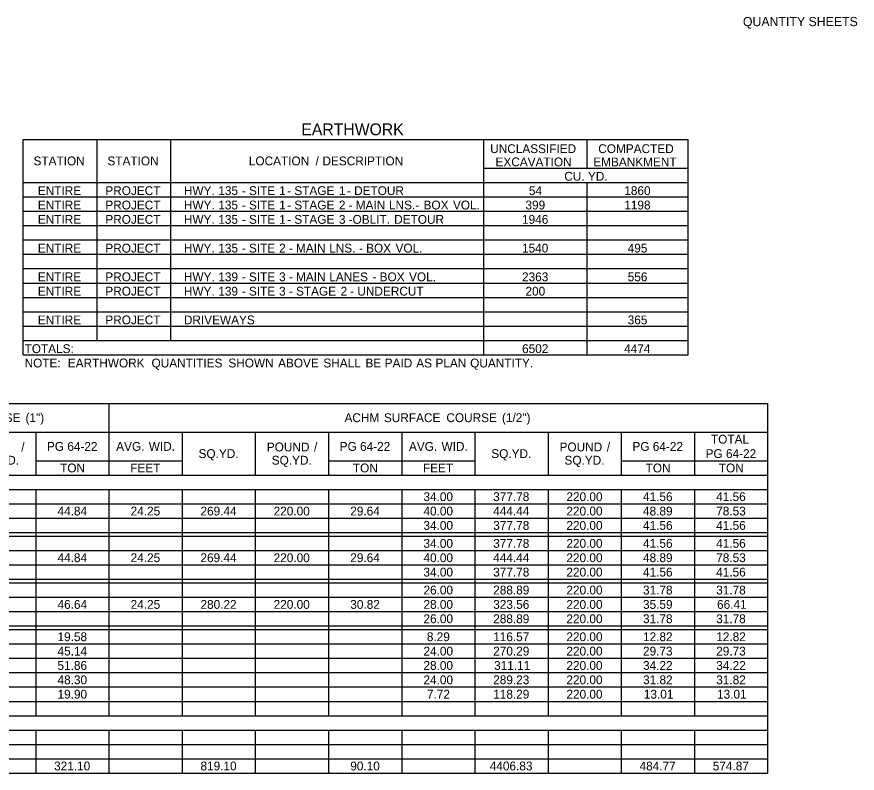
# Model space of a CAD drawing. Extents: x 1955554 to 1962042, y 565952 to 568347.
# Drawn here: x 1959623 to 1960194, y 566455 to 566969 of the extents above; entities that cross this region are included whole.
import ezdxf

# ---------------------------------------------------------------- set-up
doc = ezdxf.new("R2010")
doc.units = 0
doc.layers.add('Default', color=7, linetype='Continuous')
doc.layers.add('STAMP', color=7, linetype='Continuous')

msp = doc.modelspace()

# ---------------------------------------------------------------- linework, layer by layer
at = {"layer": 'Default'}
for p, q in [((1959627.42, 566885.45), (1960079.33, 566885.45)), ((1959627.42, 566739.2), (1959627.42, 566885.45)), ((1959627.42, 566739.2), (1959627.42, 566885.45)), ((1959677.63, 566748.95), (1959677.63, 566885.45)), ((1959727.84, 566748.95), (1959727.84, 566885.45)), ((1959940.39, 566739.2), (1959940.39, 566885.45)), ((1960010.59, 566865.95), (1960010.59, 566885.45)), ((1960079.33, 566739.2), (1960079.33, 566885.45)), ((1960079.33, 566739.2), (1960079.33, 566885.45)), ((1959940.39, 566865.95), (1960079.33, 566865.95)), ((1959627.42, 566856.2), (1960079.33, 566856.2)), ((1959677.63, 566748.95), (1959677.63, 566856.2)), ((1959727.84, 566826.95), (1959727.84, 566856.2)), ((1959940.39, 566826.95), (1959940.39, 566856.2)), ((1960010.59, 566739.2), (1960010.59, 566856.2)), ((1959627.42, 566846.45), (1960079.33, 566846.45)), ((1959627.42, 566836.7), (1960079.33, 566836.7)), ((1959627.42, 566826.95), (1960079.33, 566826.95)), ((1959627.42, 566817.2), (1960079.33, 566817.2)), ((1959727.84, 566748.95), (1959727.84, 566817.2)), ((1959940.39, 566748.95), (1959940.39, 566817.2)), ((1959627.42, 566807.45), (1960079.33, 566807.45)), ((1959627.42, 566797.7), (1960079.33, 566797.7)), ((1959627.42, 566787.95), (1960079.33, 566787.95)), ((1959627.42, 566778.2), (1960079.33, 566778.2)), ((1959627.42, 566768.45), (1960079.33, 566768.45)), ((1959627.42, 566758.7), (1960079.33, 566758.7)), ((1959627.42, 566748.95), (1959677.63, 566748.95)), ((1959627.42, 566748.95), (1960079.33, 566748.95)), ((1959627.42, 566739.2), (1960079.33, 566739.2)), ((1958693.85, 566706.28), (1960133.43, 566706.28)), ((1959685.91, 566686.78), (1959685.91, 566706.28)), ((1959685.91, 566657.53), (1959685.91, 566706.28)), ((1960133.43, 566455.22), (1960133.43, 566706.28)), ((1960133.43, 566455.22), (1960133.43, 566706.28)), ((1959033.15, 566686.78), (1960133.43, 566686.78)), ((1959636.18, 566657.53), (1959636.18, 566686.78)), ((1959735.63, 566686.78), (1959785.36, 566686.78)), ((1959735.63, 566657.53), (1959735.63, 566686.78)), ((1959785.36, 566657.53), (1959785.36, 566686.78)), ((1959835.08, 566657.53), (1959835.08, 566686.78)), ((1959884.81, 566657.53), (1959884.81, 566686.78)), ((1959934.53, 566686.78), (1959984.26, 566686.78)), ((1959934.53, 566657.53), (1959934.53, 566686.78)), ((1959984.26, 566657.53), (1959984.26, 566686.78)), ((1960033.98, 566657.53), (1960033.98, 566686.78)), ((1960083.71, 566657.53), (1960083.71, 566686.78)), ((1959636.18, 566667.28), (1959735.63, 566667.28)), ((1959685.91, 566657.53), (1959685.91, 566667.28)), ((1959735.63, 566657.53), (1959735.63, 566667.28)), ((1959835.08, 566667.28), (1959934.53, 566667.28)), ((1959884.81, 566657.53), (1959884.81, 566667.28)), ((1959934.53, 566657.53), (1959934.53, 566667.28)), ((1960033.98, 566667.28), (1960133.43, 566667.28)), ((1958693.85, 566657.53), (1960133.43, 566657.53)), ((1959536.73, 566657.53), (1959735.63, 566657.53)), ((1959735.63, 566657.53), (1959934.53, 566657.53)), ((1959934.53, 566657.53), (1960133.43, 566657.53)), ((1958693.85, 566647.78), (1960133.43, 566647.78)), ((1959636.18, 566494.22), (1959636.18, 566647.78)), ((1959636.18, 566494.22), (1959636.18, 566647.78)), ((1959685.91, 566494.22), (1959685.91, 566647.78)), ((1959685.91, 566494.22), (1959685.91, 566647.78)), ((1959735.63, 566494.22), (1959735.63, 566647.78)), ((1959735.63, 566494.22), (1959735.63, 566647.78)), ((1959785.36, 566494.22), (1959785.36, 566647.78)), ((1959785.36, 566494.22), (1959785.36, 566647.78)), ((1959835.08, 566494.22), (1959835.08, 566647.78)), ((1959835.08, 566494.22), (1959835.08, 566647.78)), ((1959884.81, 566494.22), (1959884.81, 566647.78)), ((1959884.81, 566494.22), (1959884.81, 566647.78)), ((1959934.53, 566494.22), (1959934.53, 566647.78)), ((1959934.53, 566494.22), (1959934.53, 566647.78)), ((1959984.26, 566494.22), (1959984.26, 566647.78)), ((1959984.26, 566494.22), (1959984.26, 566647.78)), ((1960033.98, 566494.22), (1960033.98, 566647.78)), ((1960033.98, 566494.22), (1960033.98, 566647.78)), ((1960083.71, 566494.22), (1960083.71, 566647.78)), ((1960083.71, 566494.22), (1960083.71, 566647.78)), ((1958693.85, 566638.03), (1960133.43, 566638.03)), ((1958693.85, 566628.28), (1960133.43, 566628.28)), ((1958693.85, 566618.53), (1960133.43, 566618.53)), ((1958693.85, 566616.09), (1960133.43, 566616.09)), ((1958693.85, 566606.34), (1960133.43, 566606.34)), ((1958693.85, 566596.59), (1960133.43, 566596.59)), ((1958693.85, 566586.84), (1960133.43, 566586.84)), ((1958693.85, 566584.4), (1960133.43, 566584.4)), ((1958693.85, 566574.65), (1960133.43, 566574.65)), ((1958693.85, 566564.9), (1960133.43, 566564.9)), ((1958693.85, 566555.15), (1960133.43, 566555.15)), ((1958693.85, 566552.72), (1960133.43, 566552.72)), ((1958693.85, 566542.97), (1960133.43, 566542.97)), ((1958693.85, 566533.22), (1960133.43, 566533.22)), ((1958693.85, 566523.47), (1960133.43, 566523.47)), ((1958693.85, 566513.72), (1960133.43, 566513.72)), ((1958693.85, 566503.97), (1960133.43, 566503.97)), ((1958693.85, 566494.22), (1960133.43, 566494.22)), ((1958693.85, 566494.22), (1960133.43, 566494.22)), ((1958693.85, 566484.47), (1960133.43, 566484.47)), ((1959636.18, 566455.22), (1959636.18, 566484.47)), ((1959636.18, 566455.22), (1959636.18, 566484.47)), ((1959685.91, 566455.22), (1959685.91, 566484.47)), ((1959685.91, 566455.22), (1959685.91, 566484.47)), ((1959735.63, 566455.22), (1959735.63, 566484.47)), ((1959735.63, 566455.22), (1959735.63, 566484.47)), ((1959785.36, 566455.22), (1959785.36, 566484.47)), ((1959785.36, 566455.22), (1959785.36, 566484.47)), ((1959835.08, 566455.22), (1959835.08, 566484.47)), ((1959835.08, 566455.22), (1959835.08, 566484.47)), ((1959884.81, 566455.22), (1959884.81, 566484.47)), ((1959884.81, 566455.22), (1959884.81, 566484.47)), ((1959934.53, 566455.22), (1959934.53, 566484.47)), ((1959934.53, 566455.22), (1959934.53, 566484.47)), ((1959984.26, 566455.22), (1959984.26, 566484.47)), ((1959984.26, 566455.22), (1959984.26, 566484.47)), ((1960033.98, 566455.22), (1960033.98, 566484.47)), ((1960033.98, 566455.22), (1960033.98, 566484.47)), ((1960083.71, 566455.22), (1960083.71, 566484.47)), ((1960083.71, 566455.22), (1960083.71, 566484.47)), ((1958693.85, 566474.72), (1960133.43, 566474.72)), ((1958693.85, 566464.97), (1960133.43, 566464.97)), ((1958693.85, 566455.22), (1960133.43, 566455.22))]:
    msp.add_line(p, q, dxfattribs=at)

# ---------------------------------------------------------------- texts
for s, height, p in [('EARTHWORK', 8, (1959816.43, 566888.28)), ('UNCLASSIFIED', 6, (1959944.72, 566876.15)), ('COMPACTED', 6, (1960018.15, 566876.15)), ('STATION', 6, (1959634.46, 566867.83)), ('STATION', 6, (1959684.67, 566867.83)), ('LOCATION', 6, (1959780.75, 566867.83)), (' /', 6, (1959823.86, 566867.83)), (' DESCRIPTION', 6, (1959828.53, 566867.83)), ('EXCAVATION', 6, (1959948.34, 566867.15)), ('EMBANKMENT', 6, (1960014.77, 566867.15)), ('CU.', 6, (1959995.07, 566857.4)), (' YD.', 6, (1960008.93, 566857.4)), ('ENTIRE', 6, (1959637.37, 566847.65)), ('PROJECT', 6, (1959683.25, 566847.65)), ('HWY.', 6, (1959736.62, 566847.65)), (' 135', 6, (1959757.77, 566847.65)), (' -', 6, (1959773.75, 566847.65)), (' SITE', 6, (1959778.6, 566847.65)), (' 1', 6, (1959799.12, 566847.65)), (' -', 6, (1959804.57, 566847.65)), (' STAGE', 6, (1959809.42, 566847.65)), (' 1', 6, (1959839.72, 566847.65)), (' -', 6, (1959845.17, 566847.65)), (' DETOUR', 6, (1959850.03, 566847.65)), ('54', 6, (1959971.04, 566847.65)), ('1860', 6, (1960035.84, 566847.65)), ('ENTIRE', 6, (1959637.37, 566837.9)), ('PROJECT', 6, (1959683.25, 566837.9)), ('HWY.', 6, (1959736.62, 566837.9)), (' 135', 6, (1959757.77, 566837.9)), (' SITE', 6, (1959778.6, 566837.9)), (' 1', 6, (1959799.12, 566837.9)), (' STAGE', 6, (1959809.42, 566837.9)), (' 2', 6, (1959839.72, 566837.9)), (' MAIN', 6, (1959851.12, 566837.9)), (' LNS.-', 6, (1959873.73, 566837.9)), (' BOX', 6, (1959897.22, 566837.9)), (' VOL.', 6, (1959917.2, 566837.9)), ('399', 6, (1959968.69, 566837.9)), ('1198', 6, (1960035.83, 566837.9)), (' -', 6, (1959773.75, 566837.9)), (' -', 6, (1959804.57, 566837.9)), (' -', 6, (1959846.27, 566837.9)), ('ENTIRE', 6, (1959637.37, 566828.15)), ('PROJECT', 6, (1959683.25, 566828.15)), ('HWY.', 6, (1959736.62, 566828.15)), (' 135', 6, (1959757.77, 566828.15)), (' SITE', 6, (1959778.6, 566828.15)), (' 1', 6, (1959799.12, 566828.15)), (' STAGE', 6, (1959809.42, 566828.15)), (' 3', 6, (1959839.72, 566828.15)), (' -OBLIT.', 6, (1959846.33, 566828.15)), (' DETOUR', 6, (1959877.27, 566828.15)), ('1946', 6, (1959966.36, 566828.15)), (' -', 6, (1959773.75, 566828.15)), (' -', 6, (1959804.57, 566828.15)), ('ENTIRE', 6, (1959637.37, 566808.65)), ('PROJECT', 6, (1959683.25, 566808.65)), ('HWY.', 6, (1959736.62, 566808.65)), (' 135', 6, (1959757.77, 566808.65)), (' SITE', 6, (1959778.6, 566808.65)), (' 2', 6, (1959799.12, 566808.65)), (' MAIN', 6, (1959810.52, 566808.65)), (' LNS.', 6, (1959833.12, 566808.65)), (' BOX', 6, (1959858.21, 566808.65)), (' VOL.', 6, (1959878.19, 566808.65)), ('1540', 6, (1959966.37, 566808.65)), ('495', 6, (1960038.14, 566808.65)), (' -', 6, (1959773.75, 566808.65)), (' -', 6, (1959805.66, 566808.65)), (' -', 6, (1959853.35, 566808.65)), ('ENTIRE', 6, (1959637.37, 566789.15)), ('PROJECT', 6, (1959683.25, 566789.15)), ('HWY.', 6, (1959736.62, 566789.15)), (' 139', 6, (1959757.77, 566789.15)), (' -', 6, (1959773.71, 566789.15)), (' SITE', 6, (1959778.57, 566789.15)), (' 3', 6, (1959799.08, 566789.15)), (' -', 6, (1959805.69, 566789.15)), (' MAIN', 6, (1959810.55, 566789.15)), (' LANES', 6, (1959833.15, 566789.15)), (' -', 6, (1959862.53, 566789.15)), (' BOX', 6, (1959867.39, 566789.15)), (' VOL.', 6, (1959887.37, 566789.15)), ('2363', 6, (1959966.36, 566789.15)), ('556', 6, (1960038.16, 566789.15)), ('ENTIRE', 6, (1959637.37, 566779.4)), ('PROJECT', 6, (1959683.25, 566779.4)), ('HWY.', 6, (1959736.62, 566779.4)), (' 139', 6, (1959757.77, 566779.4)), (' -', 6, (1959773.71, 566779.4)), (' SITE', 6, (1959778.57, 566779.4)), (' 3', 6, (1959799.08, 566779.4)), (' -', 6, (1959805.69, 566779.4)), (' STAGE', 6, (1959810.55, 566779.4)), (' 2', 6, (1959840.85, 566779.4)), (' -', 6, (1959847.39, 566779.4)), (' UNDERCUT', 6, (1959852.25, 566779.4)), ('200', 6, (1959968.7, 566779.4)), ('ENTIRE', 6, (1959637.37, 566759.9)), ('PROJECT', 6, (1959683.25, 566759.9)), ('DRIVEWAYS', 6, (1959736.62, 566759.9)), ('365', 6, (1960038.14, 566759.9)), ('TOTALS:', 6, (1959628.39, 566740.4)), ('6502', 6, (1959966.38, 566740.4)), ('4474', 6, (1960035.74, 566740.4)), ('NOTE:', 6, (1959628.39, 566730.65)), ('  EARTHWORK', 6, (1959653.28, 566730.65)), (' QUANTITIES', 6, (1959712.41, 566730.65)), (' SHOWN', 6, (1959764.61, 566730.65)), (' ABOVE', 6, (1959798.39, 566730.65)), (' SHALL', 6, (1959829.16, 566730.65)), (' BE', 6, (1959857.75, 566730.65)), (' PAID', 6, (1959870.82, 566730.65)), (' AS', 6, (1959892.27, 566730.65)), (' PLAN', 6, (1959905.34, 566730.65)), (' QUANTITY.', 6, (1959928.89, 566730.65)), (' COURSE', 6, (1959589, 566693.53)), (' (1")', 6, (1959626.78, 566693.53)), ('ACHM', 6, (1959845.74, 566693.53)), (' SURFACE', 6, (1959870.29, 566693.53)), (' COURSE', 6, (1959912.73, 566693.53)), (' (1/2")', 6, (1959950.51, 566693.53)), ('TOTAL', 6, (1960094.73, 566678.9)), (' /', 6, (1959623.92, 566673.65)), ('PG', 6, (1959643.57, 566674.03)), (' 64-22', 6, (1959655.18, 566674.03)), ('AVG.', 6, (1959690.62, 566674.03)), (' WID.', 6, (1959710.54, 566674.03)), ('POUND', 6, (1959792.96, 566673.65)), (' /', 6, (1959822.82, 566673.65)), ('PG', 6, (1959842.47, 566674.03)), (' 64-22', 6, (1959854.08, 566674.03)), ('AVG.', 6, (1959889.52, 566674.03)), (' WID.', 6, (1959909.44, 566674.03)), ('POUND', 6, (1959991.86, 566673.65)), (' /', 6, (1960021.72, 566673.65)), ('PG', 6, (1960041.37, 566674.03)), (' 64-22', 6, (1960052.98, 566674.03)), ('SQ.YD.', 6, (1959746.57, 566669.15)), ('SQ.YD.', 6, (1959945.47, 566669.15)), ('PG', 6, (1960091.1, 566669.15)), (' 64-22', 6, (1960102.71, 566669.15)), ('SQ.YD.', 6, (1959597.4, 566664.65)), ('SQ.YD.', 6, (1959796.3, 566664.65)), ('SQ.YD.', 6, (1959995.2, 566664.65)), ('TON', 6, (1959652.53, 566659.4)), ('FEET', 6, (1959700.14, 566659.4)), ('TON', 6, (1959851.43, 566659.4)), ('FEET', 6, (1959899.04, 566659.4)), ('TON', 6, (1960050.33, 566659.4)), ('TON', 6, (1960100.06, 566659.4)), ('34.00', 6, (1959899.39, 566639.9)), ('377.78', 6, (1959946.77, 566639.9)), ('220.00', 6, (1959996.51, 566639.9)), ('41.56', 6, (1960048.55, 566639.9)), ('41.56', 6, (1960098.28, 566639.9)), ('44.84', 6, (1959650.76, 566630.15)), ('24.25', 6, (1959700.45, 566630.15)), ('269.44', 6, (1959747.88, 566630.15)), ('220.00', 6, (1959797.61, 566630.15)), ('29.64', 6, (1959849.66, 566630.15)), ('40.00', 6, (1959899.39, 566630.15)), ('444.44', 6, (1959946.78, 566630.15)), ('220.00', 6, (1959996.51, 566630.15)), ('48.89', 6, (1960048.55, 566630.15)), ('78.53', 6, (1960098.28, 566630.15)), ('34.00', 6, (1959899.39, 566620.4)), ('377.78', 6, (1959946.77, 566620.4)), ('220.00', 6, (1959996.51, 566620.4)), ('41.56', 6, (1960048.55, 566620.4)), ('41.56', 6, (1960098.28, 566620.4)), ('34.00', 6, (1959899.39, 566608.22)), ('377.78', 6, (1959946.77, 566608.22)), ('220.00', 6, (1959996.51, 566608.22)), ('41.56', 6, (1960048.55, 566608.22)), ('41.56', 6, (1960098.28, 566608.22)), ('44.84', 6, (1959650.76, 566598.47)), ('24.25', 6, (1959700.45, 566598.47)), ('269.44', 6, (1959747.88, 566598.47)), ('220.00', 6, (1959797.61, 566598.47)), ('29.64', 6, (1959849.66, 566598.47)), ('40.00', 6, (1959899.39, 566598.47)), ('444.44', 6, (1959946.78, 566598.47)), ('220.00', 6, (1959996.51, 566598.47)), ('48.89', 6, (1960048.55, 566598.47)), ('78.53', 6, (1960098.28, 566598.47)), ('34.00', 6, (1959899.39, 566588.72)), ('377.78', 6, (1959946.77, 566588.72)), ('220.00', 6, (1959996.51, 566588.72)), ('41.56', 6, (1960048.55, 566588.72)), ('41.56', 6, (1960098.28, 566588.72)), ('26.00', 6, (1959899.39, 566576.53)), ('288.89', 6, (1959946.77, 566576.53)), ('220.00', 6, (1959996.51, 566576.53)), ('31.78', 6, (1960048.55, 566576.53)), ('31.78', 6, (1960098.27, 566576.53)), ('46.64', 6, (1959650.76, 566566.78)), ('24.25', 6, (1959700.45, 566566.78)), ('280.22', 6, (1959747.9, 566566.78)), ('220.00', 6, (1959797.61, 566566.78)), ('30.82', 6, (1959849.68, 566566.78)), ('28.00', 6, (1959899.39, 566566.78)), ('323.56', 6, (1959946.77, 566566.78)), ('220.00', 6, (1959996.51, 566566.78)), ('35.59', 6, (1960048.55, 566566.78)), ('66.41', 6, (1960098.86, 566566.78)), ('26.00', 6, (1959899.39, 566557.03)), ('288.89', 6, (1959946.77, 566557.03)), ('220.00', 6, (1959996.51, 566557.03)), ('31.78', 6, (1960048.55, 566557.03)), ('31.78', 6, (1960098.27, 566557.03)), ('19.58', 6, (1959650.75, 566544.84)), ('8.29', 6, (1959901.7, 566544.84)), ('116.57', 6, (1959946.77, 566544.84)), ('220.00', 6, (1959996.51, 566544.84)), ('12.82', 6, (1960048.58, 566544.84)), ('12.82', 6, (1960098.31, 566544.84)), ('45.14', 6, (1959650.76, 566535.09)), ('24.00', 6, (1959899.39, 566535.09)), ('270.29', 6, (1959946.77, 566535.09)), ('220.00', 6, (1959996.51, 566535.09)), ('29.73', 6, (1960048.55, 566535.09)), ('29.73', 6, (1960098.28, 566535.09)), ('51.86', 6, (1959650.75, 566525.34)), ('28.00', 6, (1959899.39, 566525.34)), ('311.11', 6, (1959947.35, 566525.34)), ('220.00', 6, (1959996.51, 566525.34)), ('34.22', 6, (1960048.58, 566525.34)), ('34.22', 6, (1960098.31, 566525.34)), ('48.30', 6, (1959650.76, 566515.59)), ('24.00', 6, (1959899.39, 566515.59)), ('289.23', 6, (1959946.77, 566515.59)), ('220.00', 6, (1959996.51, 566515.59)), ('31.82', 6, (1960048.58, 566515.59)), ('31.82', 6, (1960098.31, 566515.59)), ('19.90', 6, (1959650.76, 566505.84)), ('7.72', 6, (1959901.74, 566505.84)), ('118.29', 6, (1959946.77, 566505.84)), ('220.00', 6, (1959996.51, 566505.84)), ('13.01', 6, (1960049.13, 566505.84)), ('13.01', 6, (1960098.86, 566505.84)), ('321.10', 6, (1959648.44, 566457.09)), ('819.10', 6, (1959747.89, 566457.09)), ('90.10', 6, (1959849.67, 566457.09)), ('4406.83', 6, (1959944.43, 566457.09)), ('484.77', 6, (1960046.22, 566457.09)), ('574.87', 6, (1960095.94, 566457.09))]:
    msp.add_text(s, height=height, dxfattribs=at).set_placement(p)
at = {"layer": 'STAMP'}
msp.add_text('QUANTITY SHEETS', height=6.25, rotation=360, dxfattribs=at).set_placement((1960116.44, 566962.32))

doc.saveas('drawing.dxf')
